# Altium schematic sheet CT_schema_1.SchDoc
size 515 x 464 mm
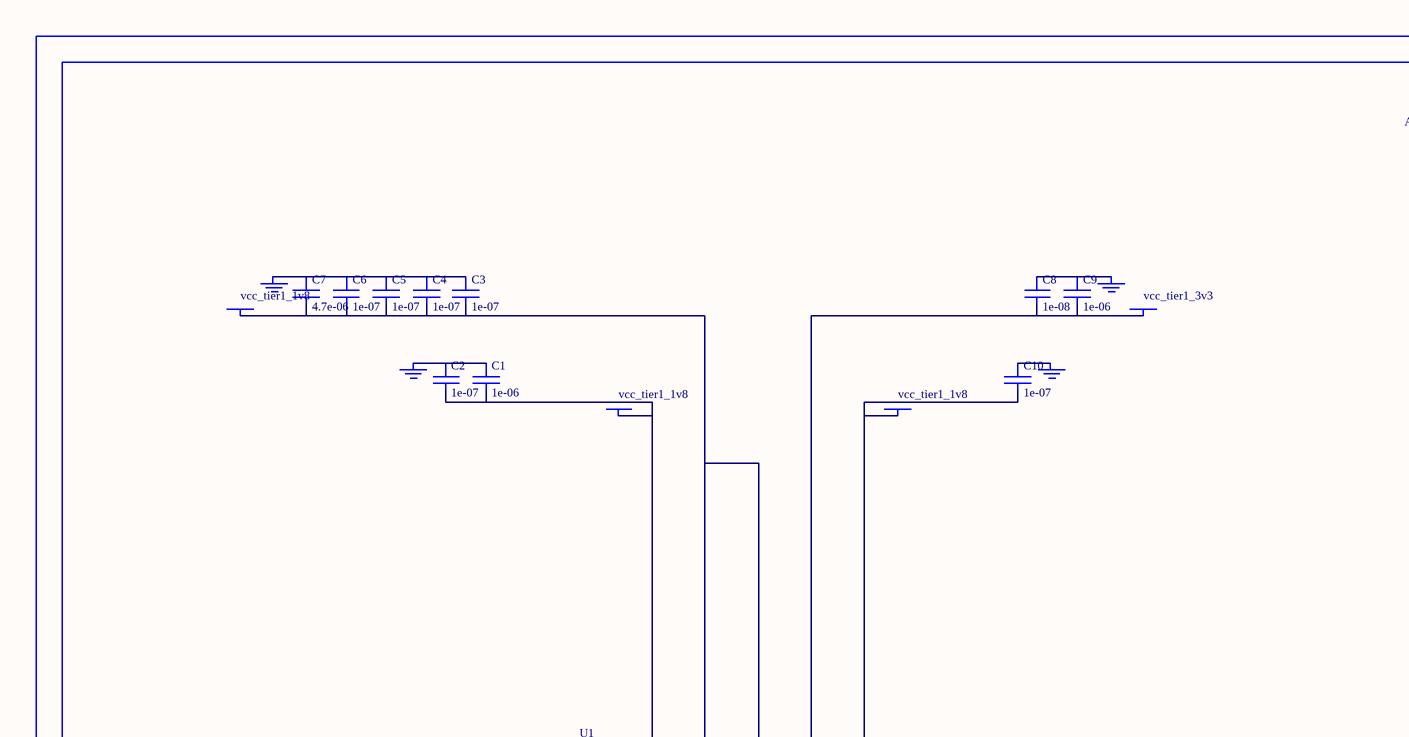
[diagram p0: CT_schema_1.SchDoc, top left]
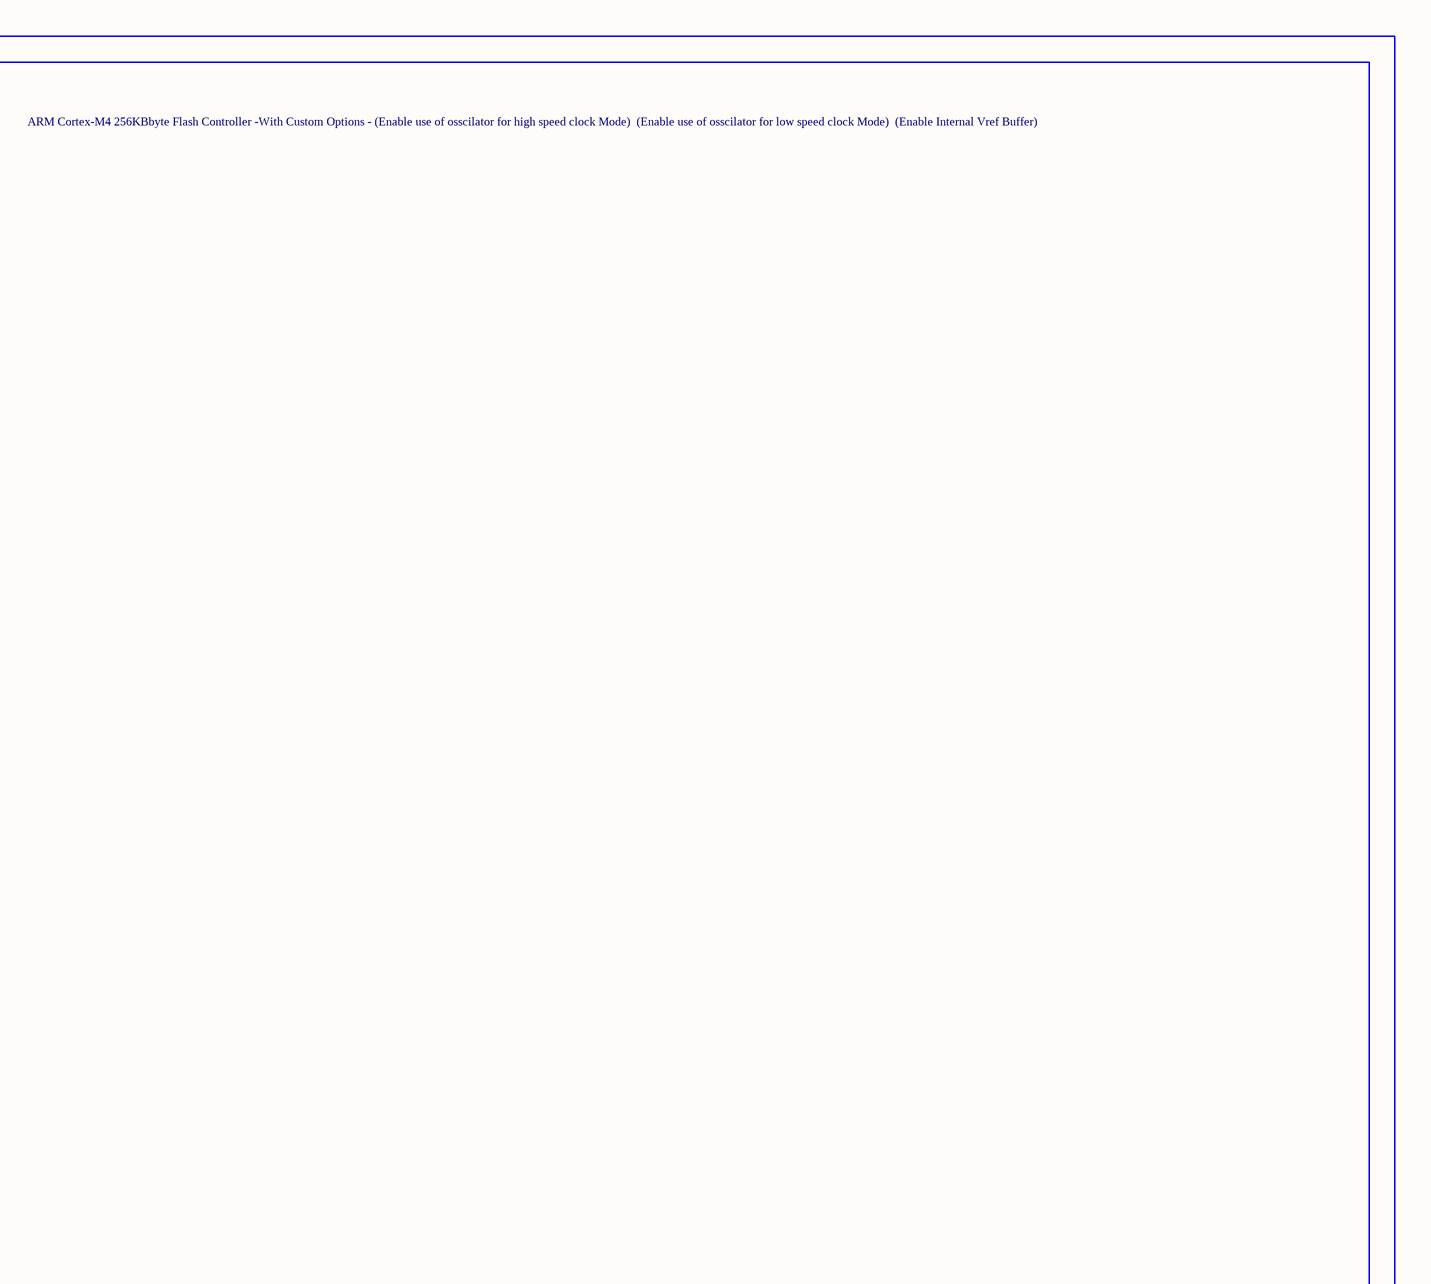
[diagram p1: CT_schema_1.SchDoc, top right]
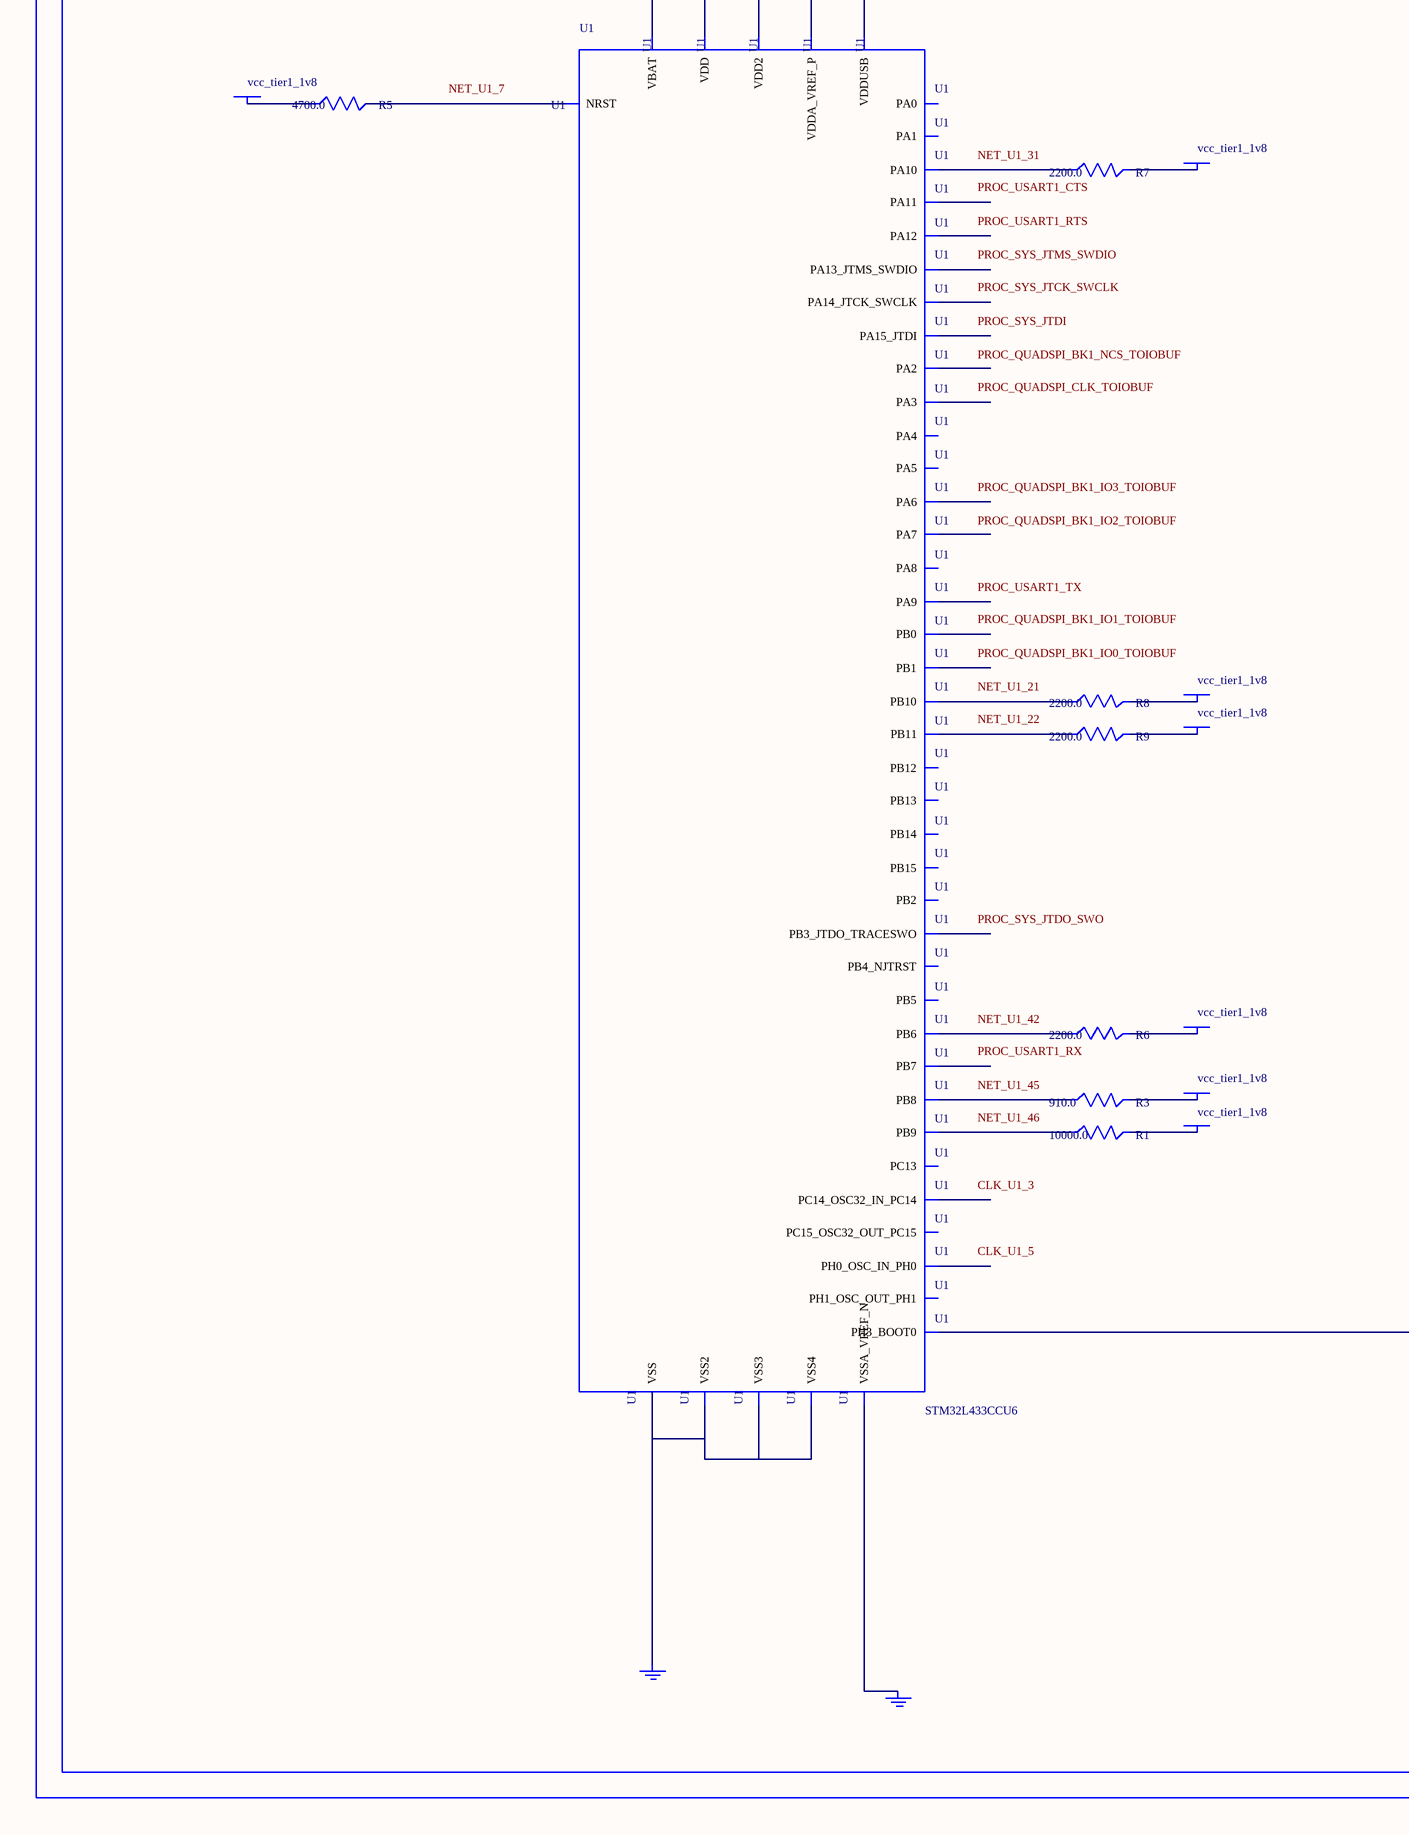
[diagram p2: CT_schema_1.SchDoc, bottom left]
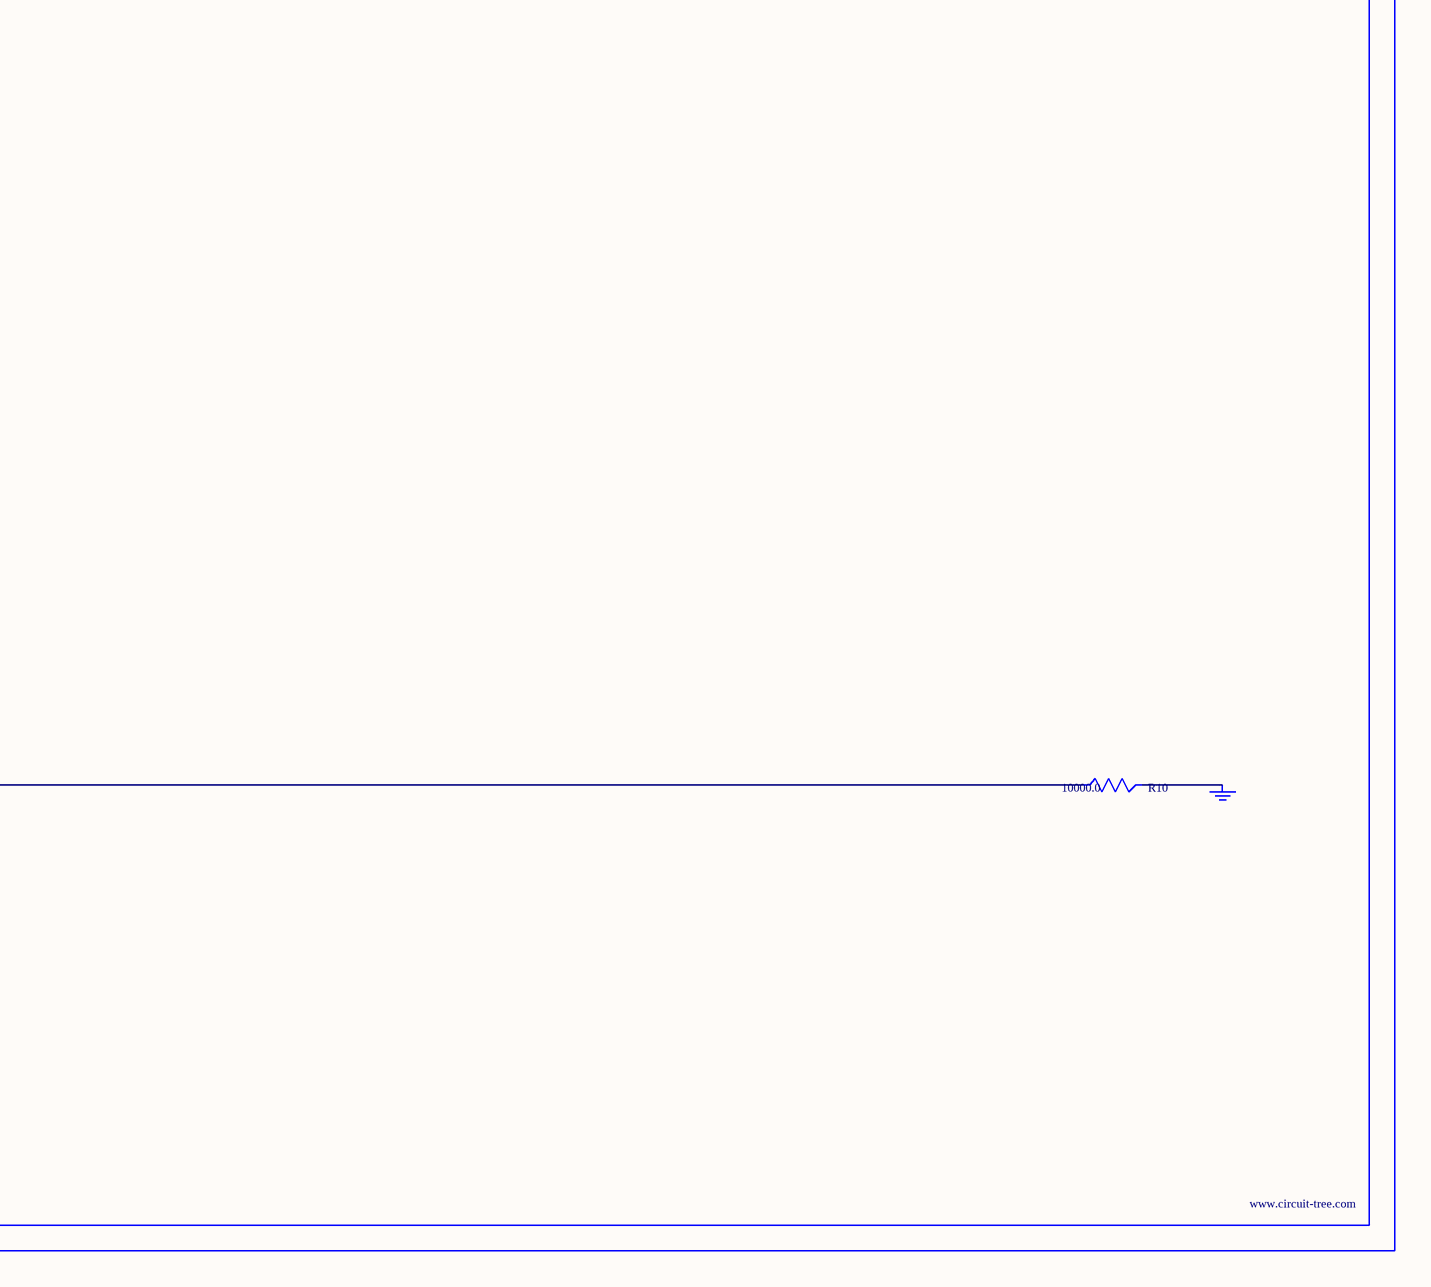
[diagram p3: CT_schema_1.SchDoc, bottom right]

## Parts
BORDER0  (no value)
C1  1e-06  [C0603]
C2  1e-07  [C0603]
C3  1e-07  [C0603]
C4  1e-07  [C0603]
C5  1e-07  [C0603]
C6  1e-07  [C0603]
C7  4.7e-06  [C0603]
C8  1e-08  [C0603]
C9  1e-06  [C0603]
C10  1e-07  [C0603]
GND_INSTANCE_0_0  (no value)
GND_INSTANCE_0_1  (no value)
GND_INSTANCE_0_2  (no value)
GND_INSTANCE_0_3  (no value)
GND_INSTANCE_0_4  (no value)
GND_INSTANCE_0_5  (no value)
GND_INSTANCE_0_6  (no value)
POWER_INSTANCE_0_0  vcc_tier1_1v8
POWER_INSTANCE_0_1  vcc_tier1_3v3
POWER_INSTANCE_0_2  vcc_tier1_1v8
POWER_INSTANCE_0_3  vcc_tier1_1v8
POWER_INSTANCE_0_4  vcc_tier1_1v8
POWER_INSTANCE_0_5  vcc_tier1_1v8
POWER_INSTANCE_0_6  vcc_tier1_1v8
POWER_INSTANCE_0_7  vcc_tier1_1v8
POWER_INSTANCE_0_8  vcc_tier1_1v8
POWER_INSTANCE_0_9  vcc_tier1_1v8
POWER_INSTANCE_0_10  vcc_tier1_1v8
R1  10000.0  [R0603]
R3  910.0  [R0603]
R5  4700.0  [R0603]
R6  2200.0  [R0603]
R7  2200.0  [R0603]
R8  2200.0  [R0603]
R9  2200.0  [R0603]
R10  10000.0  [R0603]
U1  STM32L433CCU6  [UFQFPN48]

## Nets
NetC1_1: C1.1 C2.1 GND_INSTANCE_0_0.0(GND)
NetC1_2: C1.2 C2.2 POWER_INSTANCE_0_0.0(PWR) U1.1(VBAT)
NetC3_1: C3.1 C4.1 C5.1 C6.1 C7.1 GND_INSTANCE_0_3.0(GND)
NetC3_2: C3.2 C4.2 C5.2 C6.2 C7.2 POWER_INSTANCE_0_2.0(PWR) U1.24(VDD) U1.48(VDD2)
NetC8_1: C8.1 C9.1 GND_INSTANCE_0_2.0(GND)
NetC8_2: C8.2 C9.2 POWER_INSTANCE_0_1.0(PWR) U1.9(VDDA_VREF_P)
NetC10_1: C10.1 GND_INSTANCE_0_4.0(GND)
NetC10_2: C10.2 POWER_INSTANCE_0_3.0(PWR) U1.36(VDDUSB)
NetGND_INSTANCE_0_1_0: GND_INSTANCE_0_1.0(GND) U1.8(VSSA_VREF_N)
NetGND_INSTANCE_0_5_0: GND_INSTANCE_0_5.0(GND) R10.2
NetGND_INSTANCE_0_6_0: GND_INSTANCE_0_6.0(GND) U1.23(VSS) U1.35(VSS2) U1.47(VSS3) U1.49(VSS4)
NetPOWER_INSTANCE_0_4_0: POWER_INSTANCE_0_4.0(PWR) R5.1
NetPOWER_INSTANCE_0_5_0: POWER_INSTANCE_0_5.0(PWR) R8.2
NetPOWER_INSTANCE_0_6_0: POWER_INSTANCE_0_6.0(PWR) R9.2
NetPOWER_INSTANCE_0_7_0: POWER_INSTANCE_0_7.0(PWR) R7.2
NetPOWER_INSTANCE_0_8_0: POWER_INSTANCE_0_8.0(PWR) R6.2
NetPOWER_INSTANCE_0_9_0: POWER_INSTANCE_0_9.0(PWR) R3.2
NetPOWER_INSTANCE_0_10_0: POWER_INSTANCE_0_10.0(PWR) R1.2
NetR1_1: R1.1 U1.46(PB9)
NetR3_1: R3.1 U1.45(PB8)
NetR5_2: R5.2 U1.7(NRST)
NetR6_1: R6.1 U1.42(PB6)
NetR7_1: R7.1 U1.31(PA10)
NetR8_1: R8.1 U1.21(PB10)
NetR9_1: R9.1 U1.22(PB11)
NetR10_1: R10.1 U1.44(PH3_BOOT0)

Not connected (* = marked no-connect by the designer): U1 2(PC13) 3(PC14_OSC32_IN_PC14) 4(PC15_OSC32_OUT_PC15) 5(PH0_OSC_IN_PH0) 6(PH1_OSC_OUT_PH1) 10(PA0) 11(PA1) 12(PA2) 13(PA3) 14(PA4) 15(PA5) 16(PA6) 17(PA7) 18(PB0) 19(PB1) 20(PB2) 25(PB12) 26(PB13) 27(PB14) 28(PB15) 29(PA8) 30(PA9) 32(PA11) 33(PA12) 34(PA13_JTMS_SWDIO) 37(PA14_JTCK_SWCLK) 38(PA15_JTDI) 39(PB3_JTDO_TRACESWO) 40(PB4_NJTRST) 41(PB5) 43(PB7)

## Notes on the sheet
- Labels drawn without touching a wire or pin: CLK_U1_3, CLK_U1_5, NET_U1_7, NET_U1_21, NET_U1_22, NET_U1_31, NET_U1_42, NET_U1_45, NET_U1_46, PROC_QUADSPI_BK1_IO0_TOIOBUF, PROC_QUADSPI_BK1_IO1_TOIOBUF, PROC_QUADSPI_BK1_IO2_TOIOBUF, PROC_QUADSPI_BK1_IO3_TOIOBUF, PROC_QUADSPI_BK1_NCS_TOIOBUF, PROC_QUADSPI_CLK_TOIOBUF, PROC_SYS_JTCK_SWCLK, PROC_SYS_JTDI, PROC_SYS_JTDO_SWO, PROC_SYS_JTMS_SWDIO, PROC_USART1_CTS, PROC_USART1_RTS, PROC_USART1_RX, PROC_USART1_TX

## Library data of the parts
BORDER0 = BORDER_PAGE0
C1 C9 = C0603C105K3RACTU
C2-C6 C10 = 06035C104K4Z2A
C7 = GRM188R6YA475KE15D
C8 = 06035C103K4Z2A
GND_INSTANCE_0_0-GND_INSTANCE_0_6 = GND
POWER_INSTANCE_0_0-POWER_INSTANCE_0_10 = PWR
R1 R10 = RC0603JR-0710KL
R3 = RC0603JR-07910RL
R5 = RC0603JR-074K7L
R6-R9 = RC0603JR-072K2L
